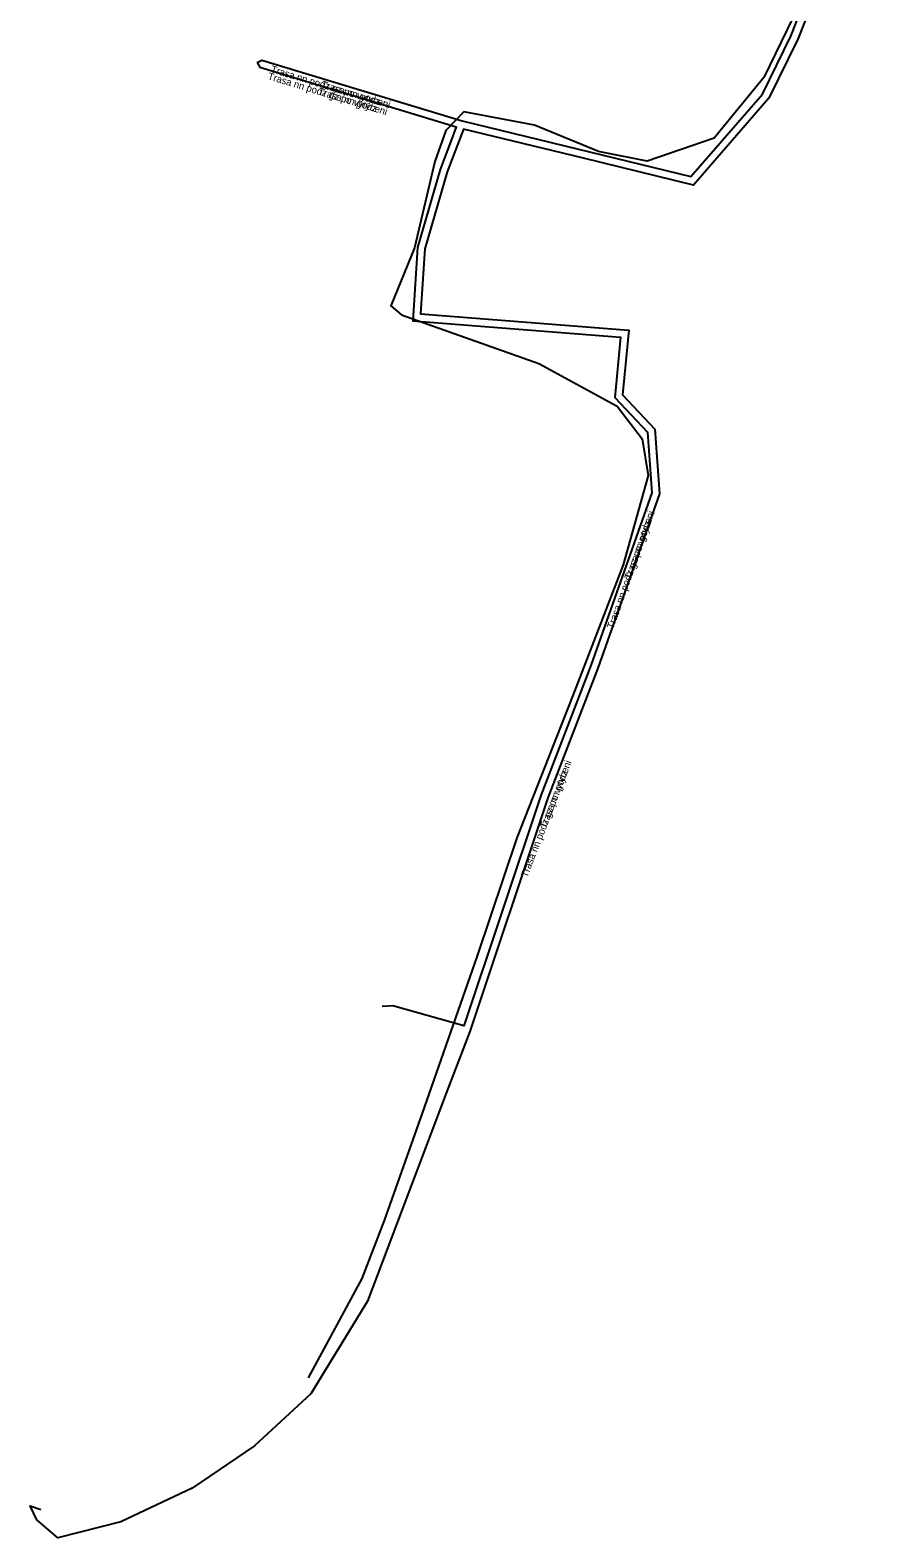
# Model space of a CAD drawing. Extents: x -528168 to -527720, y -1080003 to -1079672.
# Drawn here: x -527866.1 to -527807.3, y -1080002.6 to -1079897 of the extents above; entities that cross this region are included whole.
import ezdxf

# ---------------------------------------------------------------- set-up
doc = ezdxf.new("R2010")
doc.units = 0
doc.layers.add('Popiskový text - Ostatní atributy Trasy', color=7, linetype='Continuous')
doc.layers.add('Spojnice NN', color=7, linetype='Continuous')

msp = doc.modelspace()

# ---------------------------------------------------------------- linework, layer by layer
at = {"layer": 'Spojnice NN'}
for points in [[(-527834.85, -1079903.58), (-527819.81, -1079907.25), (-527814.79, -1079901.47), (-527812.8, -1079897.42), (-527808.66, -1079886.9), (-527805.73, -1079880.72), (-527801.23, -1079869.11), (-527790.88, -1079841.9), (-527784.91, -1079826.27), (-527772.54, -1079793.21), (-527753.38, -1079800.34), (-527752.44, -1079799.43), (-527750.93, -1079796.43), (-527748.47, -1079789.63)], [(-527751.84, -1079801.69), (-527753.24, -1079800.96), (-527772.22, -1079793.89), (-527784.41, -1079826.45), (-527790.38, -1079842.1), (-527794.83, -1079853.58), (-527800.73, -1079869.3), (-527805.23, -1079880.94), (-527808.17, -1079887.12), (-527812.31, -1079897.64), (-527814.34, -1079901.77), (-527819.63, -1079907.85), (-527827.33, -1079905.97)], [(-527751.84, -1079801.69), (-527753.24, -1079800.96), (-527772.22, -1079793.89), (-527784.41, -1079826.45), (-527790.38, -1079842.1), (-527794.83, -1079853.58), (-527800.73, -1079869.3), (-527805.23, -1079880.94), (-527808.17, -1079887.12), (-527812.31, -1079897.64), (-527814.34, -1079901.77), (-527819.63, -1079907.85), (-527827.33, -1079905.97)], [(-527811.84, -1079894.44), (-527814.69, -1079900.32), (-527818.17, -1079904.57), (-527822.86, -1079906.18), (-527826.27, -1079905.49), (-527830.75, -1079903.64), (-527835.7, -1079902.72), (-527836.97, -1079904.02), (-527837.73, -1079906.19), (-527839.16, -1079912.25), (-527840.82, -1079916.31), (-527840.06, -1079916.94), (-527830.46, -1079920.34), (-527824.97, -1079923.33), (-527823.22, -1079925.62), (-527822.79, -1079928.19), (-527824.54, -1079934.43), (-527828.06, -1079943.58), (-527831.99, -1079953.56), (-527834.76, -1079961.8), (-527838.49, -1079972.42), (-527841.27, -1079980.35), (-527842.84, -1079984.41), (-527846.61, -1079991.37)], [(-527811.84, -1079894.44), (-527814.69, -1079900.32), (-527818.17, -1079904.57), (-527822.86, -1079906.18), (-527826.27, -1079905.49), (-527830.75, -1079903.64), (-527835.7, -1079902.72), (-527836.97, -1079904.02), (-527837.73, -1079906.19), (-527839.16, -1079912.25), (-527840.82, -1079916.31), (-527840.06, -1079916.94), (-527830.46, -1079920.34), (-527824.97, -1079923.33), (-527823.22, -1079925.62), (-527822.79, -1079928.19), (-527824.54, -1079934.43), (-527828.06, -1079943.58), (-527831.99, -1079953.56), (-527834.76, -1079961.8), (-527838.49, -1079972.42), (-527841.27, -1079980.35), (-527842.84, -1079984.41), (-527846.61, -1079991.37)], [(-527850.18, -1079899.27), (-527849.84, -1079899.09), (-527835.83, -1079903.34), (-527834.85, -1079903.58)], [(-527850.18, -1079899.27), (-527849.84, -1079899.09), (-527835.83, -1079903.34), (-527834.85, -1079903.58)], [(-527850.18, -1079899.27), (-527849.98, -1079899.59), (-527836.24, -1079903.77), (-527836.64, -1079904.83)], [(-527850.18, -1079899.27), (-527849.98, -1079899.59), (-527836.24, -1079903.77), (-527836.64, -1079904.83)], [(-527827.33, -1079905.97), (-527835.73, -1079903.92), (-527836.86, -1079906.92), (-527838.44, -1079912.31), (-527838.73, -1079916.85), (-527824.15, -1079918.01), (-527824.58, -1079922.53), (-527822.32, -1079924.93), (-527822, -1079929.46), (-527826.32, -1079941.67), (-527829.81, -1079950.76), (-527835.28, -1079967.12), (-527836.93, -1079971.43), (-527842.45, -1079986), (-527846.41, -1079992.47), (-527850.37, -1079996.13), (-527854.72, -1079999.09), (-527859.72, -1080001.43), (-527864.12, -1080002.56), (-527865.61, -1080001.31), (-527866.07, -1080000.32), (-527865.33, -1080000.58)], [(-527827.33, -1079905.97), (-527835.73, -1079903.92), (-527836.86, -1079906.92), (-527838.44, -1079912.31), (-527838.73, -1079916.85), (-527824.15, -1079918.01), (-527824.58, -1079922.53), (-527822.32, -1079924.93), (-527822, -1079929.46), (-527826.32, -1079941.67), (-527829.81, -1079950.76), (-527835.28, -1079967.12), (-527836.93, -1079971.43), (-527842.45, -1079986), (-527846.41, -1079992.47), (-527850.37, -1079996.13), (-527854.72, -1079999.09), (-527859.72, -1080001.43), (-527864.12, -1080002.56), (-527865.61, -1080001.31), (-527866.07, -1080000.32), (-527865.33, -1080000.58)], [(-527836.64, -1079904.83), (-527837.35, -1079906.76), (-527838.95, -1079912.22), (-527839.28, -1079917.34), (-527824.72, -1079918.49), (-527825.13, -1079922.72), (-527822.83, -1079925.15), (-527822.53, -1079929.39), (-527826.81, -1079941.49), (-527830.3, -1079950.58), (-527835.7, -1079966.72), (-527840.67, -1079965.32), (-527841.43, -1079965.37)], [(-527836.64, -1079904.83), (-527837.35, -1079906.76), (-527838.95, -1079912.22), (-527839.28, -1079917.34), (-527824.72, -1079918.49), (-527825.13, -1079922.72), (-527822.83, -1079925.15), (-527822.53, -1079929.39), (-527826.81, -1079941.49), (-527830.3, -1079950.58), (-527835.7, -1079966.72), (-527840.67, -1079965.32), (-527841.43, -1079965.37)]]:
    msp.add_lwpolyline(points, dxfattribs=at)

# ---------------------------------------------------------------- texts
at = {"layer": 'Popiskový text - Ostatní atributy Trasy'}
for s, rotation, p in [('Trasa nn podz gz po vytyceni', 343.1239, (-527849.26, -1079899.94)), ('Trasa nn podz gz po vytyceni', 343.1184, (-527849.47, -1079900.43)), ('Trasa nn podz', 343.1239, (-527845.74, -1079901.01)), ('Trasa nn podz', 343.1184, (-527845.95, -1079901.5)), ('Trasa nn podz gz po vytyceni', 70.5251, (-527825.23, -1079938.96)), ('Trasa nn podz', 70.5251, (-527824, -1079935.49)), ('Trasa nn podz gz po vytyceni', 68.9976, (-527831.26, -1079956.36)), ('Trasa nn podz', 68.9976, (-527829.94, -1079952.92))]:
    msp.add_text(s, height=0.5, rotation=rotation, dxfattribs=at).set_placement(p)

doc.saveas('drawing.dxf')
